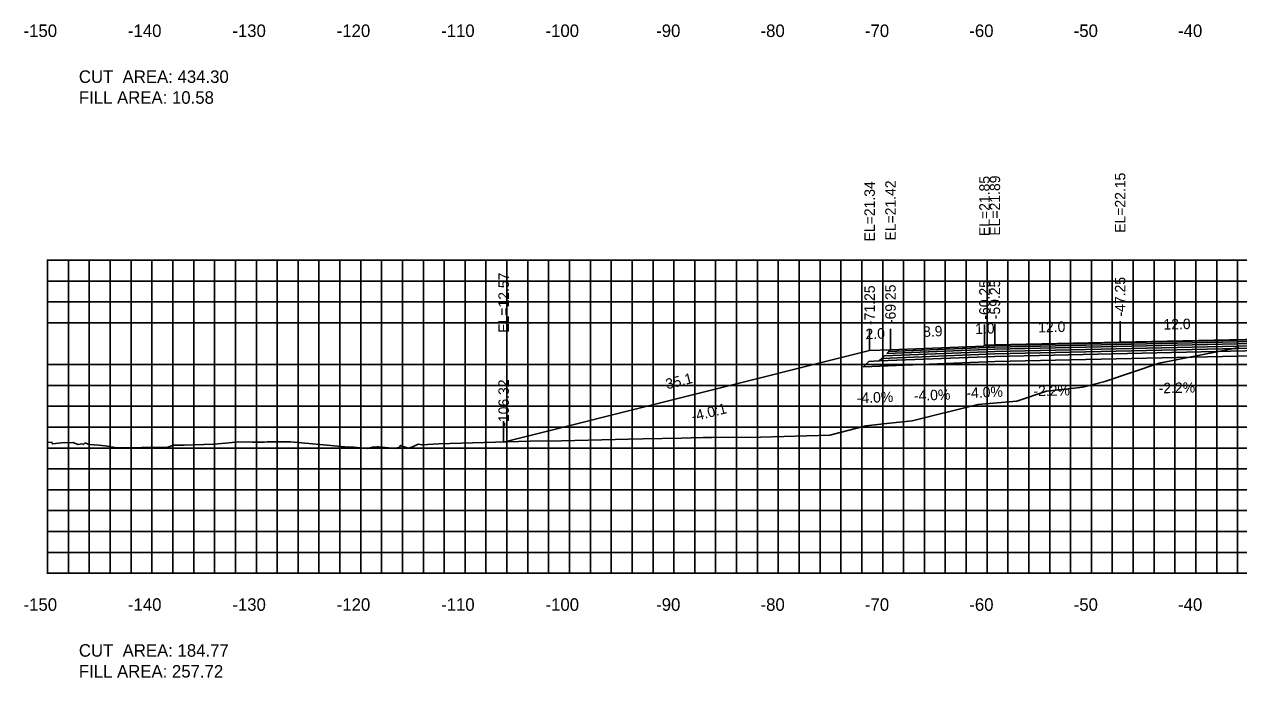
# Model space of a CAD drawing. Extents: x 1800880 to 1818864, y 245271 to 250560.
# Drawn here: x 1806218.8 to 1806335.1, y 250089.4 to 250152 of the extents above; entities that cross this region are included whole.
import ezdxf

# ---------------------------------------------------------------- set-up
doc = ezdxf.new("R2010")
doc.units = 0
for name, color, linetype in [('ANNO-SHT', 7, 'Continuous'), ('ANNO-TXT', 7, 'Continuous'), ('AXIS', 7, 'Continuous'), ('CL-CNST', 7, 'Continuous'), ('DESIGN - DRAINAGE - Bridges', 7, 'Continuous'), ('DRAINAGETXT', 7, 'Continuous'), ('great seal', 7, 'Continuous'), ('Level 37', 7, 'Continuous'), ('Level 46', 7, 'Continuous'), ('Level 62', 7, 'Continuous'), ('SHT-BDR', 7, 'Continuous'), ('SHT-BNDRY', 7, 'Continuous')]:
    doc.layers.add(name, color=color, linetype=linetype)

msp = doc.modelspace()

# ---------------------------------------------------------------- linework, layer by layer
at = {"layer": 'ANNO-SHT'}
for points in [[(1806359.75, 250121.28), (1806311.75, 250120.22), (1806300.68, 250119.78), (1806300.92, 250120.02), (1806311.75, 250120.45), (1806359.75, 250121.51), (1806371.75, 250121.24), (1806383, 250120.79), (1806383, 250120.56), (1806371.75, 250121.01)], [(1806383, 250121.02), (1806383, 250120.79), (1806371.75, 250121.24), (1806359.75, 250121.51), (1806311.75, 250120.45), (1806300.92, 250120.02), (1806301.16, 250120.26), (1806311.75, 250120.68), (1806359.75, 250121.74), (1806371.75, 250121.47)]]:
    msp.add_lwpolyline(points, close=True, dxfattribs=at)
at = {"layer": 'AXIS'}
msp.add_lwpolyline([(1806311.75, 250121.1), (1806301.59, 250120.69), (1806301.75, 250120.85), (1806310.68, 250121.21), (1806311.75, 250121.25), (1806359.75, 250122.31), (1806371.75, 250122.04), (1806381.75, 250121.64), (1806381.75, 250121.49), (1806371.75, 250121.89), (1806359.75, 250122.16)], close=True, dxfattribs=at)
at = {"layer": 'CL-CNST'}
msp.add_lwpolyline([(1806221, 250111.98), (1806221.41, 250111.97), (1806221.46, 250111.83), (1806222.35, 250111.94), (1806223.42, 250111.96), (1806223.93, 250111.78), (1806224.27, 250111.82), (1806224.4, 250111.79), (1806224.44, 250111.77), (1806224.6, 250111.92), (1806224.65, 250111.9), (1806224.9, 250111.8), (1806225.04, 250111.76), (1806225.88, 250111.72), (1806226.53, 250111.63), (1806227.44, 250111.49), (1806229.47, 250111.46), (1806229.58, 250111.46), (1806230.04, 250111.49), (1806231.95, 250111.48), (1806232.39, 250111.48), (1806232.51, 250111.53), (1806233.06, 250111.71), (1806234.09, 250111.71), (1806236.92, 250111.81), (1806238.03, 250111.91), (1806239.31, 250112.01), (1806240.63, 250112), (1806241.54, 250111.99), (1806241.78, 250112), (1806242.03, 250112.02), (1806242.98, 250112.01), (1806244.27, 250112.01), (1806248.12, 250111.66), (1806249.8, 250111.51), (1806250.35, 250111.5), (1806251.65, 250111.39), (1806252.13, 250111.5), (1806252.59, 250111.55), (1806252.62, 250111.55), (1806252.67, 250111.55), (1806252.71, 250111.55), (1806254.3, 250111.4), (1806254.75, 250111.51), (1806254.79, 250111.69), (1806255.56, 250111.41), (1806255.9, 250111.51), (1806256.5, 250111.8), (1806256.87, 250111.75), (1806258.46, 250111.83), (1806268.27, 250112.11), (1806268.97, 250112.1), (1806276.65, 250112.29), (1806278.06, 250112.32), (1806281.73, 250112.39), (1806282.65, 250112.41), (1806283.79, 250112.44), (1806284.64, 250112.44), (1806289.33, 250112.46), (1806295.95, 250112.66), (1806299.39, 250113.57), (1806301.68, 250113.81), (1806303.84, 250114.04), (1806310.13, 250115.61), (1806312.34, 250115.79), (1806313.85, 250115.92), (1806316.71, 250116.87), (1806317.93, 250117.01), (1806320.16, 250117.26), (1806322.28, 250117.8), (1806327.49, 250119.57), (1806335.13, 250121.08)], dxfattribs=at)
at = {"layer": 'DESIGN - DRAINAGE - Bridges'}
for p, q in [((1806220.94, 250129.43), (1806221, 250129.43)), ((1806221, 250099.43), (1806221, 250129.43)), ((1806220.94, 250119.43), (1806221, 250119.43)), ((1806220.94, 250109.43), (1806221, 250109.43)), ((1806220.94, 250099.43), (1806221, 250099.43)), ((1806221, 250099.43), (1806521, 250099.43)), ((1806221, 250099.37), (1806221, 250099.43)), ((1806231, 250099.37), (1806231, 250099.43)), ((1806241, 250099.37), (1806241, 250099.43)), ((1806251, 250099.37), (1806251, 250099.43)), ((1806261, 250099.37), (1806261, 250099.43)), ((1806271, 250099.37), (1806271, 250099.43)), ((1806281, 250099.37), (1806281, 250099.43)), ((1806291, 250099.37), (1806291, 250099.43)), ((1806301, 250099.37), (1806301, 250099.43)), ((1806311, 250099.37), (1806311, 250099.43)), ((1806321, 250099.37), (1806321, 250099.43)), ((1806331, 250099.37), (1806331, 250099.43))]:
    msp.add_line(p, q, dxfattribs=at)
at = {"layer": 'great seal'}
msp.add_lwpolyline([(1806311.75, 250120.91), (1806301.4, 250120.5), (1806301.59, 250120.69), (1806311.75, 250121.1), (1806359.75, 250122.16), (1806371.75, 250121.89), (1806381.75, 250121.49), (1806383, 250121.44), (1806383, 250121.25), (1806371.75, 250121.7), (1806359.75, 250121.97)], close=True, dxfattribs=at)
at = {"layer": 'Level 37'}
for p, q in [((1806299.75, 250120.77), (1806299.75, 250122.77)), ((1806301.75, 250120.85), (1806301.75, 250122.85)), ((1806310.75, 250121.28), (1806310.75, 250123.28)), ((1806311.75, 250121.32), (1806311.75, 250123.32)), ((1806323.75, 250121.58), (1806323.75, 250123.58)), ((1806264.69, 250112), (1806264.69, 250114))]:
    msp.add_line(p, q, dxfattribs=at)
msp.add_lwpolyline([(1806311.75, 250121.25), (1806310.68, 250121.21), (1806310.75, 250121.28), (1806311.75, 250121.32), (1806323.75, 250121.58), (1806335.75, 250121.85), (1806347.75, 250122.11), (1806359.75, 250122.38), (1806371.75, 250122.11), (1806371.75, 250122.04), (1806359.75, 250122.31)], close=True, dxfattribs=at)
at = {"layer": 'Level 46'}
for p, q in [((1806221, 250129.43), (1806521, 250129.43)), ((1806221, 250099.43), (1806221, 250129.43)), ((1806223, 250099.43), (1806223, 250129.43)), ((1806225, 250099.43), (1806225, 250129.43)), ((1806227, 250099.43), (1806227, 250129.43)), ((1806229, 250099.43), (1806229, 250129.43)), ((1806231, 250099.43), (1806231, 250129.43)), ((1806233, 250099.43), (1806233, 250129.43)), ((1806235, 250099.43), (1806235, 250129.43)), ((1806237, 250099.43), (1806237, 250129.43)), ((1806239, 250099.43), (1806239, 250129.43)), ((1806241, 250099.43), (1806241, 250129.43)), ((1806243, 250099.43), (1806243, 250129.43)), ((1806245, 250099.43), (1806245, 250129.43)), ((1806247, 250099.43), (1806247, 250129.43)), ((1806249, 250099.43), (1806249, 250129.43)), ((1806251, 250099.43), (1806251, 250129.43)), ((1806253, 250099.43), (1806253, 250129.43)), ((1806255, 250099.43), (1806255, 250129.43)), ((1806257, 250099.43), (1806257, 250129.43)), ((1806259, 250099.43), (1806259, 250129.43)), ((1806261, 250099.43), (1806261, 250129.43)), ((1806263, 250099.43), (1806263, 250129.43)), ((1806265, 250099.43), (1806265, 250129.43)), ((1806267, 250099.43), (1806267, 250129.43)), ((1806269, 250099.43), (1806269, 250129.43)), ((1806271, 250099.43), (1806271, 250129.43)), ((1806273, 250099.43), (1806273, 250129.43)), ((1806275, 250099.43), (1806275, 250129.43)), ((1806277, 250099.43), (1806277, 250129.43)), ((1806279, 250099.43), (1806279, 250129.43)), ((1806281, 250099.43), (1806281, 250129.43)), ((1806283, 250099.43), (1806283, 250129.43)), ((1806285, 250099.43), (1806285, 250129.43)), ((1806287, 250099.43), (1806287, 250129.43)), ((1806289, 250099.43), (1806289, 250129.43)), ((1806291, 250099.43), (1806291, 250129.43)), ((1806293, 250099.43), (1806293, 250129.43)), ((1806295, 250099.43), (1806295, 250129.43)), ((1806297, 250099.43), (1806297, 250129.43)), ((1806299, 250099.43), (1806299, 250129.43)), ((1806301, 250099.43), (1806301, 250129.43)), ((1806303, 250099.43), (1806303, 250129.43)), ((1806305, 250099.43), (1806305, 250129.43)), ((1806307, 250099.43), (1806307, 250129.43)), ((1806309, 250099.43), (1806309, 250129.43)), ((1806311, 250099.43), (1806311, 250129.43)), ((1806313, 250099.43), (1806313, 250129.43)), ((1806315, 250099.43), (1806315, 250129.43)), ((1806317, 250099.43), (1806317, 250129.43)), ((1806319, 250099.43), (1806319, 250129.43)), ((1806321, 250099.43), (1806321, 250129.43)), ((1806323, 250099.43), (1806323, 250129.43)), ((1806325, 250099.43), (1806325, 250129.43)), ((1806327, 250099.43), (1806327, 250129.43)), ((1806329, 250099.43), (1806329, 250129.43)), ((1806331, 250099.43), (1806331, 250129.43)), ((1806333, 250099.43), (1806333, 250129.43)), ((1806335, 250099.43), (1806335, 250129.43)), ((1806221, 250127.43), (1806521, 250127.43)), ((1806221, 250125.43), (1806521, 250125.43)), ((1806221, 250123.43), (1806521, 250123.43)), ((1806221, 250119.43), (1806521, 250119.43)), ((1806221, 250117.43), (1806521, 250117.43)), ((1806221, 250115.43), (1806521, 250115.43)), ((1806221, 250113.43), (1806521, 250113.43)), ((1806221, 250111.43), (1806521, 250111.43)), ((1806221, 250109.43), (1806521, 250109.43)), ((1806221, 250107.43), (1806521, 250107.43)), ((1806221, 250105.43), (1806521, 250105.43)), ((1806221, 250103.43), (1806521, 250103.43)), ((1806221, 250101.43), (1806521, 250101.43)), ((1806221, 250099.43), (1806521, 250099.43))]:
    msp.add_line(p, q, dxfattribs=at)
at = {"layer": 'Level 62'}
msp.add_lwpolyline([(1806264.69, 250112), (1806299.75, 250120.77), (1806301.75, 250120.85), (1806310.68, 250121.21), (1806310.75, 250121.28), (1806311.75, 250121.32), (1806323.75, 250121.58), (1806335.75, 250121.85), (1806347.75, 250122.11), (1806359.75, 250122.38), (1806371.75, 250122.11), (1806381.75, 250121.71), (1806383, 250121.44), (1806383, 250120.06), (1806383, 250121.44), (1806384.25, 250121.71), (1806394.25, 250122.11), (1806406.25, 250122.38), (1806418.25, 250122.11), (1806430.25, 250121.85), (1806431.25, 250121.83), (1806431.32, 250121.76), (1806433.04, 250121.72)], dxfattribs=at)
at = {"layer": 'SHT-BNDRY'}
msp.add_lwpolyline([(1806383, 250120.56), (1806383, 250120.06), (1806371.75, 250120.51), (1806359.75, 250120.78), (1806311.75, 250119.72), (1806299.16, 250119.22), (1806299.68, 250119.74), (1806300.68, 250119.78), (1806311.75, 250120.22), (1806359.75, 250121.28), (1806371.75, 250121.01)], close=True, dxfattribs=at)

# ---------------------------------------------------------------- texts
for s, p in [('-150', (1806218.7, 250150.83)), ('-140', (1806228.7, 250150.83)), ('-130', (1806238.7, 250150.83)), ('-120', (1806248.7, 250150.83)), ('-110', (1806258.7, 250150.83)), ('-100', (1806268.7, 250150.83)), ('-90', (1806279.3, 250150.83)), ('-80', (1806289.3, 250150.83)), ('-70', (1806299.3, 250150.83)), ('-60', (1806309.3, 250150.83)), ('-50', (1806319.3, 250150.83)), ('-40', (1806329.3, 250150.83)), ('-150', (1806218.7, 250095.83)), ('-140', (1806228.7, 250095.83)), ('-130', (1806238.7, 250095.83)), ('-120', (1806248.7, 250095.83)), ('-110', (1806258.7, 250095.83)), ('-100', (1806268.7, 250095.83)), ('-90', (1806279.3, 250095.83)), ('-80', (1806289.3, 250095.83)), ('-70', (1806299.3, 250095.83)), ('-60', (1806309.3, 250095.83)), ('-50', (1806319.3, 250095.83)), ('-40', (1806329.3, 250095.83))]:
    msp.add_text(s, height=1.2).set_placement(p)
at = {"layer": 'ANNO-TXT'}
for s, rotation, p in [('12.0', 1.2603, (1806327.91, 250122.78)), ('2.0', 2.2906, (1806299.38, 250121.86)), ('8.9', 2.2906, (1806304.89, 250122.08)), ('1.0', 2.2906, (1806309.88, 250122.35)), ('12.0', 1.2603, (1806315.91, 250122.51)), ('35.1', 14.0362, (1806280.35, 250117.05)), ('-4.0%', 2.2906, (1806298.54, 250115.72)), ('-4.0%', 2.2906, (1806304.01, 250115.94)), ('-4.0%', 2.2906, (1806309.04, 250116.21)), ('-2.2%', 1.2603, (1806315.45, 250116.4)), ('-2.2%', 1.2603, (1806327.45, 250116.67))]:
    msp.add_text(s, height=1, rotation=rotation, dxfattribs=at).set_placement(p)
at = {"layer": 'DESIGN - DRAINAGE - Bridges'}
msp.add_text('-', height=0.0001, dxfattribs=at).set_placement((1806221, 250099.43))
at = {"layer": 'DRAINAGETXT'}
for s, p in [('CUT  AREA: 434.30', (1806224, 250146.43)), ('FILL AREA: 10.58', (1806224, 250144.43)), ('CUT  AREA: 184.77', (1806224, 250091.43)), ('FILL AREA: 257.72', (1806224, 250089.43))]:
    msp.add_text(s, height=1.2, dxfattribs=at).set_placement(p)
at = {"layer": 'Level 37'}
msp.add_text('-4.0:1', height=1, rotation=14.0362, dxfattribs=at).set_placement((1806282.82, 250113.96))
at = {"layer": 'SHT-BDR'}
for s, p in [('EL=22.15', (1806324.25, 250132.06)), ('EL=21.34', (1806300.25, 250131.24)), ('EL=21.42', (1806302.25, 250131.32)), ('EL=21.85', (1806311.25, 250131.75)), ('EL=21.89', (1806312.25, 250131.79)), ('EL=12.57', (1806265.19, 250122.48)), ('-60.25', (1806311.25, 250123.74)), ('-59.25', (1806312.25, 250123.78)), ('-47.25', (1806324.25, 250124.04)), ('-71.25', (1806300.25, 250123.23)), ('-69.25', (1806302.25, 250123.31)), ('-106.32', (1806265.19, 250113.47))]:
    msp.add_text(s, height=1, rotation=90, dxfattribs=at).set_placement(p)

doc.saveas('drawing.dxf')
